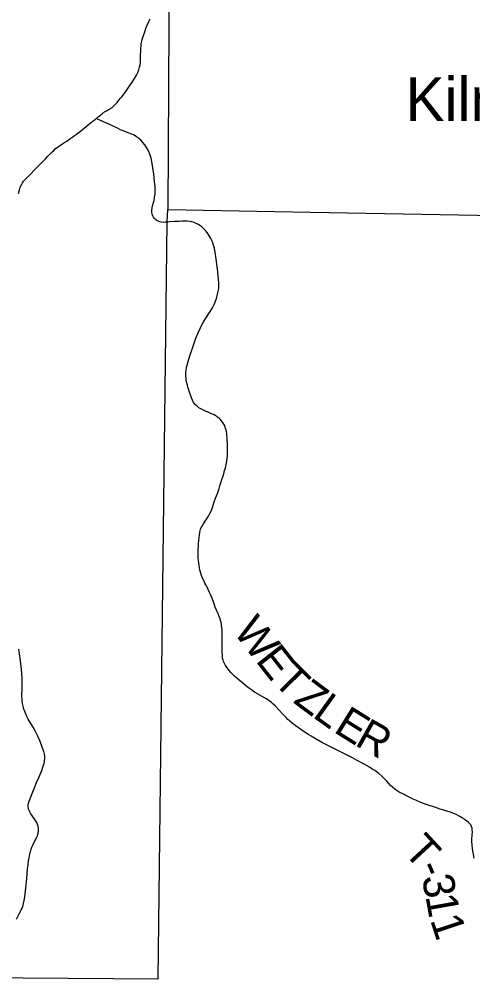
# Model space of a CAD drawing. Extents: x -10.5 to 40.6, y -3.2 to 22.
# Drawn here: x -8.513 to -7.693, y 16.022 to 17.758 of the extents above; entities that cross this region are included whole.
import ezdxf

# ---------------------------------------------------------------- set-up
doc = ezdxf.new("R2010")
doc.units = 0
for name, color, linetype in [('GM_X_Township_Road', 7, 'Continuous'), ('GM_X_Township_Road_Text', 7, 'Continuous'), ('GM_X_Township_Text', 7, 'Continuous'), ('GM_X_Unincorporated_Text', 7, 'Continuous')]:
    doc.layers.add(name, color=color, linetype=linetype)

msp = doc.modelspace()

# ---------------------------------------------------------------- linework, layer by layer
at = {"layer": 'GM_X_Township_Road'}
for points in [[(-8.3738, 17.5778), (-8.3721, 17.5792), (-8.3693, 17.5815), (-8.3667, 17.5837), (-8.3646, 17.5855), (-8.3632, 17.5867), (-8.3612, 17.5881), (-8.36, 17.589), (-8.3588, 17.5898), (-8.3573, 17.5907), (-8.3553, 17.5919), (-8.353, 17.5932), (-8.3509, 17.5944), (-8.3491, 17.5954), (-8.347, 17.5967), (-8.345, 17.5982), (-8.3435, 17.5994), (-8.3417, 17.601), (-8.34, 17.6026), (-8.3382, 17.6045), (-8.3359, 17.6069), (-8.3325, 17.611), (-8.3296, 17.6145), (-8.327, 17.6178), (-8.3235, 17.6223), (-8.3203, 17.6267), (-8.3165, 17.632), (-8.3128, 17.6374), (-8.3085, 17.6438), (-8.3043, 17.6504), (-8.3024, 17.6533), (-8.3009, 17.6563), (-8.2995, 17.6587), (-8.2984, 17.6613), (-8.2966, 17.6659), (-8.2952, 17.6707), (-8.2944, 17.675), (-8.2938, 17.6799), (-8.2934, 17.6892), (-8.293, 17.704), (-8.2925, 17.7103), (-8.2922, 17.7128), (-8.2918, 17.7154), (-8.2913, 17.7176), (-8.2906, 17.7206), (-8.2894, 17.7243), (-8.2882, 17.7284), (-8.2866, 17.7332), (-8.2846, 17.739), (-8.2832, 17.7427), (-8.2815, 17.7469), (-8.2788, 17.7532), (-8.2763, 17.7584)], [(-8.5142, 17.4423), (-8.5125, 17.4489), (-8.511, 17.4536), (-8.509, 17.4582), (-8.5068, 17.4619), (-8.505, 17.4644), (-8.5034, 17.4663), (-8.501, 17.4691), (-8.494, 17.4762), (-8.484, 17.4863), (-8.4726, 17.4978), (-8.4652, 17.5053), (-8.4609, 17.5097), (-8.4545, 17.5165), (-8.4505, 17.5204), (-8.4478, 17.5229), (-8.4434, 17.5264), (-8.4384, 17.5299), (-8.4324, 17.5338), (-8.427, 17.5373), (-8.4198, 17.5422), (-8.4157, 17.5451), (-8.4127, 17.5473), (-8.4092, 17.5498), (-8.4023, 17.5551), (-8.3883, 17.5663), (-8.379, 17.5736), (-8.3757, 17.5762), (-8.3738, 17.5778)], [(-8.2439, 17.3907), (-8.2449, 17.3906), (-8.249, 17.3903), (-8.2527, 17.3902), (-8.2558, 17.3905), (-8.2589, 17.3912), (-8.2618, 17.3922), (-8.264, 17.3934), (-8.2665, 17.3952), (-8.2682, 17.397), (-8.27, 17.3995), (-8.2713, 17.4023), (-8.2722, 17.4053), (-8.2728, 17.4089), (-8.2729, 17.412), (-8.2726, 17.4157), (-8.2717, 17.42), (-8.2691, 17.4296), (-8.268, 17.4356), (-8.2673, 17.4412), (-8.267, 17.4473), (-8.2672, 17.4548), (-8.268, 17.4634), (-8.2697, 17.4775), (-8.2715, 17.4891), (-8.2732, 17.5002), (-8.2745, 17.5062), (-8.2761, 17.5116), (-8.2778, 17.5163), (-8.2799, 17.5208), (-8.2827, 17.5256), (-8.2858, 17.5303), (-8.2893, 17.5346), (-8.2931, 17.5387), (-8.2967, 17.542), (-8.2987, 17.5435), (-8.3007, 17.545), (-8.3049, 17.5476), (-8.3093, 17.5497), (-8.3156, 17.5522), (-8.3232, 17.5549), (-8.3266, 17.5563), (-8.33, 17.5578), (-8.3364, 17.5609), (-8.3432, 17.564), (-8.3511, 17.5676), (-8.3661, 17.5743), (-8.3738, 17.5778)], [(-7.6902, 16.2404), (-7.693, 16.2574), (-7.6938, 16.2647), (-7.6942, 16.2702), (-7.6942, 16.2751), (-7.6938, 16.2819), (-7.6934, 16.2881), (-7.6935, 16.2919), (-7.694, 16.2949), (-7.695, 16.2979), (-7.6964, 16.3006), (-7.6983, 16.3031), (-7.7005, 16.3052), (-7.7039, 16.3078), (-7.7068, 16.31), (-7.7083, 16.311), (-7.7119, 16.3133), (-7.713, 16.314), (-7.7162, 16.3159), (-7.7228, 16.3193), (-7.7285, 16.3218), (-7.7331, 16.3234), (-7.7378, 16.325), (-7.7473, 16.3279), (-7.7514, 16.3292), (-7.7567, 16.331), (-7.765, 16.3337), (-7.7696, 16.3353), (-7.7714, 16.3359), (-7.7767, 16.3377), (-7.7866, 16.3413), (-7.7947, 16.3445), (-7.8003, 16.347), (-7.8104, 16.3519), (-7.8148, 16.3542), (-7.817, 16.3553), (-7.8258, 16.3601), (-7.8295, 16.3623), (-7.8336, 16.365), (-7.8379, 16.3686), (-7.8414, 16.372), (-7.8447, 16.3757), (-7.8484, 16.3799), (-7.8518, 16.3835), (-7.8572, 16.3887), (-7.8628, 16.3935), (-7.8673, 16.3969), (-7.8698, 16.3987), (-7.8744, 16.4017), (-7.8797, 16.4049), (-7.8888, 16.4102), (-7.903, 16.4179), (-7.9112, 16.4223), (-7.9211, 16.4274), (-7.9244, 16.4291), (-7.9283, 16.431), (-7.9366, 16.4352), (-7.9394, 16.4365), (-7.9449, 16.4393), (-7.956, 16.4448), (-7.9643, 16.4491), (-7.9757, 16.4555), (-7.9847, 16.4609), (-7.989, 16.4635), (-7.9937, 16.4665), (-8.0035, 16.473), (-8.0136, 16.4802), (-8.0195, 16.4848), (-8.0242, 16.4888), (-8.0269, 16.4913), (-8.0304, 16.4948), (-8.0371, 16.5021), (-8.043, 16.5084), (-8.0495, 16.5151), (-8.054, 16.5193), (-8.0568, 16.5217), (-8.0607, 16.5248), (-8.0659, 16.5283), (-8.0696, 16.5305), (-8.0776, 16.5352), (-8.0819, 16.5377), (-8.0872, 16.5409), (-8.0929, 16.5447), (-8.0984, 16.5487), (-8.1038, 16.5528), (-8.1086, 16.5567), (-8.1152, 16.5623), (-8.1235, 16.5697), (-8.1297, 16.5758), (-8.1334, 16.58), (-8.1368, 16.5844), (-8.1399, 16.5891), (-8.1421, 16.5935), (-8.1433, 16.596), (-8.144, 16.5983), (-8.1447, 16.6006), (-8.1452, 16.6033), (-8.1455, 16.606), (-8.1459, 16.614), (-8.146, 16.627), (-8.1456, 16.6418), (-8.1458, 16.6499), (-8.1461, 16.6537), (-8.1464, 16.6573), (-8.1468, 16.6605), (-8.1473, 16.6636), (-8.148, 16.6668), (-8.1489, 16.6701), (-8.1497, 16.6731), (-8.1513, 16.6772), (-8.1534, 16.6823), (-8.1563, 16.6892), (-8.1583, 16.6944), (-8.1597, 16.6987), (-8.1616, 16.7043), (-8.1635, 16.7089), (-8.165, 16.7128), (-8.1671, 16.7174), (-8.1692, 16.7219), (-8.1713, 16.7264), (-8.1732, 16.7303), (-8.1756, 16.7346), (-8.1771, 16.738), (-8.1793, 16.7424), (-8.1812, 16.7469), (-8.183, 16.7518), (-8.1849, 16.7578), (-8.186, 16.7618), (-8.1869, 16.7657), (-8.1877, 16.7701), (-8.1882, 16.7741), (-8.1888, 16.7791), (-8.1891, 16.7832), (-8.1893, 16.7886), (-8.1892, 16.793), (-8.189, 16.7983), (-8.1886, 16.8047), (-8.1884, 16.8092), (-8.1881, 16.8142), (-8.1876, 16.8201), (-8.187, 16.8252), (-8.1864, 16.8293), (-8.1857, 16.8329), (-8.1849, 16.8355), (-8.1837, 16.8382), (-8.1823, 16.8409), (-8.1797, 16.8451), (-8.1778, 16.8483), (-8.1753, 16.8518), (-8.173, 16.8554), (-8.1706, 16.859), (-8.1681, 16.8635), (-8.1659, 16.8681), (-8.1647, 16.8711), (-8.1636, 16.8746), (-8.1623, 16.8787), (-8.1609, 16.8831), (-8.1578, 16.8912), (-8.1546, 16.8999), (-8.1534, 16.9034), (-8.1516, 16.9087), (-8.1499, 16.914), (-8.1475, 16.921), (-8.1462, 16.9253), (-8.1448, 16.93), (-8.143, 16.9355), (-8.1415, 16.9413), (-8.1401, 16.9462), (-8.1387, 16.9522), (-8.1375, 16.9586), (-8.1369, 16.9631), (-8.1365, 16.9685), (-8.1362, 16.9747), (-8.1361, 16.9802), (-8.1362, 16.9865), (-8.1368, 16.9995), (-8.1375, 17.0075), (-8.1383, 17.0124), (-8.1396, 17.0172), (-8.1403, 17.0196), (-8.1412, 17.0219), (-8.1419, 17.0234), (-8.1428, 17.0253), (-8.1439, 17.027), (-8.1451, 17.0289), (-8.1475, 17.0318), (-8.1492, 17.0336), (-8.151, 17.0353), (-8.1526, 17.0367), (-8.1544, 17.038), (-8.1564, 17.0395), (-8.1585, 17.0407), (-8.1618, 17.0425), (-8.164, 17.0436), (-8.1673, 17.0452), (-8.169, 17.0459), (-8.1724, 17.0473), (-8.1736, 17.0478), (-8.1775, 17.0495), (-8.1835, 17.0525), (-8.1878, 17.0551), (-8.1913, 17.0577), (-8.194, 17.0602), (-8.1952, 17.0615), (-8.1964, 17.0631), (-8.1981, 17.0657), (-8.1988, 17.067), (-8.1996, 17.0685), (-8.2013, 17.073), (-8.2025, 17.0766), (-8.2041, 17.0812), (-8.2054, 17.0847), (-8.2069, 17.0894), (-8.2078, 17.0923), (-8.2088, 17.0959), (-8.2098, 17.0994), (-8.2103, 17.1024), (-8.2108, 17.1057), (-8.2112, 17.1093), (-8.2113, 17.1122), (-8.2114, 17.1151), (-8.2114, 17.1188), (-8.2108, 17.1237), (-8.2102, 17.1274), (-8.2095, 17.1304), (-8.2084, 17.1346), (-8.2073, 17.1388), (-8.2043, 17.1489), (-8.1992, 17.1643), (-8.1933, 17.1806), (-8.1894, 17.1904), (-8.1859, 17.1984), (-8.1831, 17.2039), (-8.18, 17.2093), (-8.1764, 17.2151), (-8.1673, 17.229), (-8.1635, 17.2354), (-8.1604, 17.2415), (-8.1578, 17.2478), (-8.1563, 17.2526), (-8.1541, 17.2603), (-8.1529, 17.2658), (-8.1522, 17.2707), (-8.1519, 17.275), (-8.152, 17.28), (-8.1524, 17.2874), (-8.1532, 17.2948), (-8.1535, 17.2978), (-8.1539, 17.3009), (-8.1551, 17.3095), (-8.1564, 17.3193), (-8.1573, 17.3279), (-8.1578, 17.3328), (-8.1589, 17.3395), (-8.1598, 17.3438), (-8.1614, 17.3491), (-8.1636, 17.3549), (-8.1665, 17.3611), (-8.1699, 17.3671), (-8.1729, 17.3717), (-8.176, 17.3757), (-8.1794, 17.3793), (-8.1826, 17.3822), (-8.1861, 17.3848), (-8.1888, 17.3864), (-8.1927, 17.3883), (-8.1965, 17.3898), (-8.2007, 17.391), (-8.205, 17.3918), (-8.2094, 17.3923), (-8.2138, 17.3922), (-8.2187, 17.3922), (-8.2237, 17.3919), (-8.2323, 17.3915), (-8.241, 17.3909), (-8.2439, 17.3907)], [(-8.518, 16.1299), (-8.5122, 16.1409), (-8.509, 16.1476), (-8.5066, 16.1533), (-8.5049, 16.1586), (-8.5037, 16.1641), (-8.5026, 16.1708), (-8.5007, 16.1868), (-8.4993, 16.2039), (-8.4977, 16.2209), (-8.4969, 16.2287), (-8.496, 16.2359), (-8.4952, 16.2409), (-8.4946, 16.2449), (-8.494, 16.2473), (-8.4935, 16.2497), (-8.4928, 16.2521), (-8.4921, 16.2545), (-8.4911, 16.2572), (-8.4899, 16.2603), (-8.4885, 16.2637), (-8.4869, 16.267), (-8.4812, 16.2786), (-8.4801, 16.2811), (-8.4794, 16.2831), (-8.4788, 16.2849), (-8.4784, 16.2867), (-8.4781, 16.2886), (-8.478, 16.2904), (-8.4779, 16.2919), (-8.478, 16.2935), (-8.4781, 16.2951), (-8.4784, 16.2965), (-8.4787, 16.298), (-8.4791, 16.2995), (-8.4799, 16.3015), (-8.4805, 16.303), (-8.4813, 16.3048), (-8.4825, 16.3068), (-8.4858, 16.3119), (-8.4921, 16.3209), (-8.4939, 16.3241), (-8.4953, 16.3276), (-8.4961, 16.3305), (-8.4965, 16.3336), (-8.4965, 16.3366), (-8.496, 16.3397), (-8.4947, 16.3438), (-8.4909, 16.3543), (-8.486, 16.3662), (-8.4815, 16.3773), (-8.4777, 16.3865), (-8.4723, 16.399), (-8.4694, 16.4066), (-8.4679, 16.4119), (-8.467, 16.4162), (-8.4666, 16.4205), (-8.4668, 16.4243), (-8.4674, 16.4285), (-8.4687, 16.4334), (-8.4712, 16.441), (-8.4752, 16.4513), (-8.4793, 16.4609), (-8.4828, 16.4682), (-8.4861, 16.4742), (-8.4965, 16.4918), (-8.4997, 16.4979), (-8.5024, 16.5042), (-8.5045, 16.51), (-8.5059, 16.5154), (-8.5069, 16.5203), (-8.5076, 16.5265), (-8.5079, 16.5339), (-8.5077, 16.5476), (-8.5078, 16.5656), (-8.5083, 16.5742), (-8.509, 16.5823), (-8.5106, 16.5971), (-8.5117, 16.6057), (-8.5136, 16.6186)]]:
    msp.add_lwpolyline(points, dxfattribs=at)
at = {"layer": 'GM_X_Township_Text'}
for points in [[(-10.5445, 19.4241), (-9.8621, 19.4152), (-9.3297, 19.4093), (-9.2736, 19.4089), (-9.2734, 18.9532), (-9.2666, 18.9242), (-9.2573, 18.7823), (-9.2552, 18.7211), (-9.2586, 18.705), (-9.2677, 18.6789), (-9.2756, 18.3974), (-9.1719, 18.3965), (-8.6421, 18.3977), (-8.2403, 18.3894), (-8.2411, 17.9704), (-8.2441, 17.4134), (-7.9861, 17.4086), (-7.6509, 17.4026), (-7.3241, 17.3974), (-6.9004, 17.4016), (-6.4692, 17.3961), (-6.192, 17.3965), (-6.1874, 16.891), (-6.062, 16.8858)], [(-10.5445, 19.4241), (-10.5445, 16.0741), (-10.3151, 16.0685), (-10.1031, 16.0664), (-9.5534, 16.0497), (-8.7017, 16.0275), (-8.5879, 16.0247), (-8.2615, 16.0223), (-8.2451, 17.3912), (-8.2441, 17.4134)]]:
    msp.add_lwpolyline(points, dxfattribs=at)

# ---------------------------------------------------------------- texts
at = {"layer": 'GM_X_Township_Road_Text'}
for s, rotation, p in [('W', 307.5312, (-8.1274, 16.6503)), ('E', 308.1791, (-8.0868, 16.5975)), ('T', 314.735, (-8.0559, 16.5589)), ('Z', 323.387, (-8.0191, 16.5227)), ('L', 324.2306, (-7.9842, 16.4968)), ('E', 328.1119, (-7.9463, 16.4696)), ('R', 330.5625, (-7.908, 16.4458)), ('T', 312.7782, (-7.8199, 16.2512)), ('-', 294.0719, (-7.7937, 16.2241)), ('3', 281.2446, (-7.7852, 16.206)), ('1', 280.0167, (-7.7784, 16.1719)), ('1', 288.2116, (-7.7702, 16.1289))]:
    msp.add_text(s, height=0.0568, rotation=rotation, dxfattribs=at).set_placement(p)
at = {"layer": 'GM_X_Unincorporated_Text'}
msp.add_text('Kilmer', height=0.07898, rotation=0, dxfattribs=at).set_placement((-7.8141, 17.5735))

doc.saveas('drawing.dxf')
